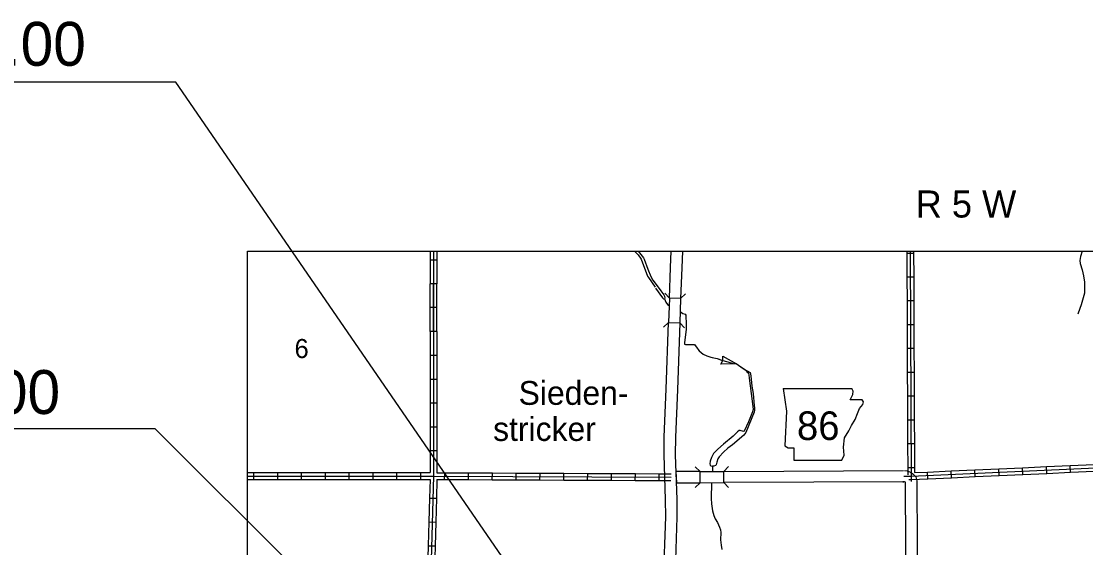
# Model space of a CAD drawing. Extents: x 982240 to 1103002, y 974866 to 1054902.
# Drawn here: x 1013608 to 1037189, y 1011477 to 1023147 of the extents above; entities that cross this region are included whole.
import ezdxf

# ---------------------------------------------------------------- set-up
doc = ezdxf.new("R2010")
doc.units = 0
for name, color, linetype in [('10', 7, 'Continuous'), ('15', 7, 'Continuous'), ('21', 7, 'Continuous'), ('24', 7, 'Continuous'), ('32', 7, 'Continuous'), ('35', 7, 'Continuous'), ('37', 7, 'Continuous'), ('43', 7, 'Continuous'), ('5', 7, 'Continuous'), ('R_Draft', 7, 'Continuous')]:
    doc.layers.add(name, color=color, linetype=linetype)

msp = doc.modelspace()

# ---------------------------------------------------------------- linework, layer by layer
at = {"layer": '10'}
for p, q in [((1028645, 1013167), (1028111, 1013164)), ((1028111, 1013164), (1028120, 1012914)), ((1028645, 1012917), (1028645, 1013167)), ((1029173, 1012919), (1029173, 1013169)), ((1028120, 1012914), (1028645, 1012917)), ((1028645, 1012917), (1028645, 1012917)), ((1033139, 1012939), (1033157, 1012938))]:
    msp.add_line(p, q, dxfattribs=at)
for points in [[(1028645, 1013167), (1029173, 1013169)], [(1029173, 1013169), (1033156, 1013188)], [(1033174, 1013187), (1033237, 1013178), (1033309, 1013153), (1033362, 1013117), (1033422, 1013046), (1033449, 1012962), (1033470, 1008617)], [(1028645, 1012917), (1029173, 1012919)], [(1033157, 1012938), (1029173, 1012919)], [(1033220, 1008616), (1033199, 1012923), (1033194, 1012928), (1033178, 1012934), (1033139, 1012939)]]:
    msp.add_lwpolyline(points, dxfattribs=at)
at = {"layer": '15'}
for p, q in [((1028215, 1017000), (1027965, 1017009)), ((1027946, 1016469), (1028196, 1016460))]:
    msp.add_line(p, q, dxfattribs=at)
for points in [[(1027965, 1017009), (1027989, 1017690), (1028005, 1018049)], [(1028256, 1018049), (1028239, 1017680), (1028215, 1017000)], [(1027965, 1017009), (1027946, 1016469)], [(1028215, 1017000), (1028196, 1016460)], [(1027488, 1005912), (1027591, 1006325), (1027648, 1006626), (1027676, 1006827), (1027714, 1007377), (1027838, 1010743), (1027884, 1012160), (1027883, 1012544), (1027847, 1013535), (1027848, 1013935), (1027894, 1014988), (1027946, 1016469)], [(1028196, 1016460), (1028144, 1014978), (1028098, 1013929), (1028097, 1013539), (1028133, 1012549), (1028134, 1012156), (1028088, 1010735), (1027964, 1007364), (1027924, 1006801), (1027895, 1006586), (1027836, 1006271), (1027730, 1005850)]]:
    msp.add_lwpolyline(points, dxfattribs=at)
at = {"layer": '21'}
for p, q in [((1030484, 1015009), (1030561, 1014502)), ((1032041, 1014950), (1032006, 1015008)), ((1031973, 1014755), (1032032, 1014874)), ((1032235, 1014755), (1031973, 1014755)), ((1032032, 1014874), (1032041, 1014950)), ((1032269, 1014713), (1032235, 1014755)), ((1030561, 1014502), (1030527, 1013732)), ((1032134, 1014451), (1032176, 1014561)), ((1032176, 1014561), (1032252, 1014654)), ((1032252, 1014654), (1032269, 1014713)), ((1031999, 1014189), (1032083, 1014316)), ((1032083, 1014316), (1032134, 1014451)), ((1031846, 1013910), (1031939, 1014070)), ((1031939, 1014070), (1031999, 1014189)), ((1031821, 1013707), (1031846, 1013910)), ((1030527, 1013732), (1030594, 1013690)), ((1030594, 1013690), (1030721, 1013690)), ((1030721, 1013690), (1030721, 1013419)), ((1031838, 1013529), (1031821, 1013707)), ((1030721, 1013419), (1031787, 1013419)), ((1031787, 1013419), (1031838, 1013529))]:
    msp.add_line(p, q, dxfattribs=at)
msp.add_lwpolyline([(1030484, 1015009), (1032006, 1015008)], dxfattribs=at)
at = {"layer": '32'}
for p, q in [((1022667, 1017855), (1022817, 1017855)), ((1033376, 1018002), (1033226, 1018002)), ((1022815, 1017327), (1022665, 1017327)), ((1033378, 1017474), (1033228, 1017474)), ((1033380, 1016946), (1033230, 1016946)), ((1022815, 1016799), (1022665, 1016799)), ((1033383, 1016418), (1033233, 1016418)), ((1022815, 1016271), (1022665, 1016271)), ((1022667, 1015743), (1022817, 1015743)), ((1033385, 1015890), (1033235, 1015890)), ((1022667, 1015215), (1022817, 1015215)), ((1033387, 1015362), (1033237, 1015362)), ((1033389, 1014834), (1033239, 1014834)), ((1022667, 1014687), (1022817, 1014687)), ((1033392, 1014306), (1033242, 1014306)), ((1022667, 1014159), (1022817, 1014159)), ((1033394, 1013778), (1033244, 1013778)), ((1022667, 1013631), (1022817, 1013631)), ((1022667, 1013631), (1022667, 1013141)), ((1022817, 1013631), (1022817, 1013140)), ((1018763, 1012991), (1018763, 1013141)), ((1019291, 1012991), (1019291, 1013141)), ((1019819, 1012991), (1019819, 1013141)), ((1020347, 1012991), (1020347, 1013141)), ((1020875, 1012991), (1020875, 1013141)), ((1021403, 1012991), (1021403, 1013141)), ((1021931, 1012991), (1021931, 1013141)), ((1022459, 1012991), (1022459, 1013141)), ((1022459, 1013141), (1022667, 1013141)), ((1022817, 1013140), (1022988, 1013139)), ((1022987, 1012989), (1022988, 1013139)), ((1023515, 1012987), (1023516, 1013137)), ((1024043, 1012984), (1024044, 1013134)), ((1024571, 1012982), (1024572, 1013132)), ((1025099, 1012979), (1025100, 1013129)), ((1025627, 1012977), (1025628, 1013127)), ((1026155, 1012974), (1026156, 1013124)), ((1026683, 1012972), (1026684, 1013122)), ((1027211, 1012969), (1027212, 1013119)), ((1027739, 1012966), (1027740, 1013116)), ((1033396, 1013250), (1033246, 1013250)), ((1033396, 1013250), (1033396, 1013141)), ((1033396, 1013141), (1033681, 1013154)), ((1033688, 1013004), (1033681, 1013154)), ((1034215, 1013028), (1034208, 1013178)), ((1034743, 1013053), (1034736, 1013202)), ((1035270, 1013077), (1035263, 1013227)), ((1035797, 1013101), (1035790, 1013251)), ((1036325, 1013125), (1036318, 1013275)), ((1036852, 1013150), (1036845, 1013300)), ((1022459, 1012991), (1022665, 1012991)), ((1022665, 1012991), (1022653, 1012578)), ((1022815, 1012990), (1022803, 1012573)), ((1022815, 1012990), (1022987, 1012989)), ((1022653, 1012578), (1022803, 1012573)), ((1022639, 1012050), (1022789, 1012046)), ((1022624, 1011522), (1022774, 1011518))]:
    msp.add_line(p, q, dxfattribs=at)
for points in [[(1022740, 1018049), (1022741, 1013064), (1022667, 1010407), (1022655, 1010251), (1022641, 1009890)], [(1022666, 1018049), (1022667, 1017855)], [(1022816, 1018049), (1022817, 1017855)], [(1033226, 1018049), (1033226, 1018002)], [(1033302, 1018049), (1033324, 1012943)], [(1033376, 1018049), (1033376, 1018002)], [(1022667, 1017855), (1022665, 1017327)], [(1022817, 1017855), (1022815, 1017327)], [(1033226, 1018002), (1033228, 1017474)], [(1033376, 1018002), (1033378, 1017474)], [(1022665, 1016799), (1022665, 1017327)], [(1022740, 1016271), (1022740, 1017327)], [(1022815, 1016799), (1022815, 1017327)], [(1033228, 1017474), (1033230, 1016946)], [(1033378, 1017474), (1033380, 1016946)], [(1033230, 1016946), (1033233, 1016418)], [(1033380, 1016946), (1033383, 1016418)], [(1022665, 1016271), (1022665, 1016799)], [(1022815, 1016271), (1022815, 1016799)], [(1033233, 1016418), (1033235, 1015890)], [(1033383, 1016418), (1033385, 1015890)], [(1022665, 1016271), (1022667, 1015743)], [(1022815, 1016271), (1022817, 1015743)], [(1022667, 1015743), (1022667, 1015215)], [(1022817, 1015743), (1022817, 1015215)], [(1033235, 1015890), (1033237, 1015362)], [(1033385, 1015890), (1033387, 1015362)], [(1022667, 1015215), (1022667, 1014687)], [(1022817, 1015215), (1022817, 1014687)], [(1033237, 1015362), (1033239, 1014834)], [(1033387, 1015362), (1033389, 1014834)], [(1033239, 1014834), (1033242, 1014306)], [(1033389, 1014834), (1033392, 1014306)], [(1022667, 1014687), (1022667, 1014159)], [(1022817, 1014687), (1022817, 1014159)], [(1033242, 1014306), (1033244, 1013778)], [(1033392, 1014306), (1033394, 1013778)], [(1022667, 1014159), (1022667, 1013631)], [(1022817, 1014159), (1022817, 1013631)], [(1033244, 1013778), (1033246, 1013250)], [(1033394, 1013778), (1033396, 1013250)], [(1033157, 1013063), (1033323, 1013061), (1038730, 1013310)], [(1036845, 1013300), (1037373, 1013324)], [(1018617, 1013141), (1018763, 1013141)], [(1018763, 1013141), (1019291, 1013141)], [(1019291, 1013141), (1019819, 1013141)], [(1019819, 1013141), (1020347, 1013141)], [(1020347, 1013141), (1020875, 1013141)], [(1020875, 1013141), (1021403, 1013141)], [(1021403, 1013141), (1021931, 1013141)], [(1021931, 1013141), (1022459, 1013141)], [(1022988, 1013139), (1023516, 1013137)], [(1023516, 1013137), (1024044, 1013134)], [(1024044, 1013134), (1024572, 1013132)], [(1024572, 1013132), (1025100, 1013129)], [(1025100, 1013129), (1025628, 1013127)], [(1025628, 1013127), (1026156, 1013124)], [(1026156, 1013124), (1026684, 1013122)], [(1026684, 1013122), (1027212, 1013119)], [(1027212, 1013119), (1027740, 1013116)], [(1027740, 1013116), (1028002, 1013115)], [(1033246, 1013250), (1033247, 1013090)], [(1033681, 1013154), (1034208, 1013178)], [(1034208, 1013178), (1034736, 1013202)], [(1034736, 1013202), (1035263, 1013227)], [(1034743, 1013053), (1035270, 1013077)], [(1035263, 1013227), (1035790, 1013251)], [(1035270, 1013077), (1035797, 1013101)], [(1035790, 1013251), (1036318, 1013275)], [(1035797, 1013101), (1036325, 1013125)], [(1036318, 1013275), (1036845, 1013300)], [(1036325, 1013125), (1036852, 1013150)], [(1036852, 1013150), (1037380, 1013174)], [(1018617, 1013064), (1022741, 1013064), (1028002, 1013039)], [(1018617, 1012991), (1018763, 1012991)], [(1018763, 1012991), (1019291, 1012991)], [(1019291, 1012991), (1019819, 1012991)], [(1019819, 1012991), (1020347, 1012991)], [(1020347, 1012991), (1020875, 1012991)], [(1020875, 1012991), (1021403, 1012991)], [(1021403, 1012991), (1021931, 1012991)], [(1021931, 1012991), (1022459, 1012991)], [(1022987, 1012989), (1023515, 1012987)], [(1023515, 1012987), (1024043, 1012984)], [(1024043, 1012984), (1024571, 1012982)], [(1024571, 1012982), (1025099, 1012979)], [(1025099, 1012979), (1025627, 1012977)], [(1025627, 1012977), (1026155, 1012974)], [(1026155, 1012974), (1026683, 1012972)], [(1026683, 1012972), (1027211, 1012969)], [(1027211, 1012969), (1027739, 1012966)], [(1027739, 1012966), (1028001, 1012965)], [(1033269, 1012988), (1033324, 1012987), (1033688, 1013004)], [(1033688, 1013004), (1034215, 1013028)], [(1034215, 1013028), (1034743, 1013053)], [(1022653, 1012578), (1022639, 1012050)], [(1022803, 1012573), (1022789, 1012046)], [(1022639, 1012050), (1022624, 1011522)], [(1022789, 1012046), (1022774, 1011518)], [(1022624, 1011522), (1022609, 1010994)], [(1022774, 1011518), (1022759, 1010990)]]:
    msp.add_lwpolyline(points, dxfattribs=at)
at = {"layer": '35'}
for points in [[(1027192, 1018049), (1027275, 1017971), (1027339, 1017873), (1027480, 1017500), (1027500, 1017467), (1027649, 1017254)], [(1027273, 1018049), (1027390, 1017902), (1027408, 1017871), (1027491, 1017649), (1027554, 1017489), (1027601, 1017406)], [(1037110, 1018049), (1037072, 1017933), (1037061, 1017846), (1037070, 1017775), (1037113, 1017634), (1037142, 1017501), (1037159, 1017365), (1037165, 1017266), (1037159, 1017123), (1037092, 1016863), (1037020, 1016673), (1037016, 1016657)], [(1027601, 1017406), (1027717, 1017249), (1027776, 1017170), (1027846, 1017080), (1027859, 1017051), (1027865, 1017007), (1027859, 1016993), (1027886, 1016917), (1027925, 1016872), (1027959, 1016846)], [(1027660, 1017232), (1027812, 1017017), (1027836, 1016997), (1027859, 1016993)], [(1028205, 1016716), (1028264, 1016668), (1028317, 1016651), (1028329, 1016631), (1028337, 1016425), (1028337, 1016385)], [(1028337, 1016385), (1028335, 1016324), (1028301, 1016018), (1028304, 1015986), (1028321, 1015978)], [(1029679, 1015400), (1029676, 1015394), (1029683, 1015379), (1029701, 1015364), (1029720, 1015340), (1029728, 1015311), (1029733, 1015237), (1029801, 1014725), (1029821, 1014542), (1029808, 1014490), (1029717, 1014267), (1029624, 1014058), (1029610, 1014050), (1029537, 1014076), (1029514, 1014074), (1029478, 1014044), (1029380, 1013947), (1029162, 1013776)], [(1029679, 1015400), (1029691, 1015399), (1029753, 1015360), (1029768, 1015288), (1029796, 1015060), (1029820, 1014892), (1029843, 1014632), (1029852, 1014579), (1029851, 1014526), (1029844, 1014483), (1029656, 1014031), (1029616, 1013975), (1029362, 1013759), (1029258, 1013683)], [(1029162, 1013776), (1029037, 1013662), (1028945, 1013563), (1028898, 1013478), (1028871, 1013398), (1028861, 1013337), (1028870, 1013304), (1028881, 1013295), (1028924, 1013284), (1028923, 1013170)], [(1029258, 1013683), (1029163, 1013595), (1029067, 1013489), (1029042, 1013450), (1029017, 1013375), (1029005, 1013317), (1028989, 1013296), (1028951, 1013284), (1028924, 1013284)], [(1028898, 1012918), (1028894, 1012565), (1028902, 1012449), (1028924, 1012295), (1028952, 1012188), (1028983, 1012117), (1029031, 1012039), (1029079, 1011936), (1029099, 1011870), (1029104, 1011814), (1029098, 1011652), (1029112, 1011534), (1029131, 1011435)]]:
    msp.add_lwpolyline(points, dxfattribs=at)
at = {"layer": '37'}
for points in [[(1027965, 1017009), (1027863, 1017119)], [(1028325, 1017102), (1028215, 1017000)], [(1027836, 1016367), (1027946, 1016469)], [(1028196, 1016460), (1028298, 1016351)], [(1028539, 1013273), (1028645, 1013167)], [(1029173, 1013169), (1029279, 1013275)], [(1028645, 1012917), (1028539, 1012811)], [(1029279, 1012813), (1029173, 1012919)]]:
    msp.add_lwpolyline(points, dxfattribs=at)
at = {"layer": '43'}
for p, q in [((1029151, 1015720), (1029450, 1015551)), ((1029152, 1015629), (1029152, 1015721)), ((1029106, 1015549), (1029152, 1015628)), ((1029450, 1015551), (1029107, 1015548)), ((1029152, 1015628), (1029152, 1015629))]:
    msp.add_line(p, q, dxfattribs=at)
for points in [[(1028321, 1015978), (1028521, 1015978), (1028578, 1015900), (1028628, 1015840), (1028717, 1015766), (1028793, 1015728), (1028885, 1015700), (1029026, 1015668), (1029118, 1015638), (1029257, 1015594), (1029381, 1015562), (1029443, 1015551), (1029464, 1015543), (1029498, 1015522), (1029679, 1015400)], [(1028321, 1015978), (1028519, 1015978)], [(1028599, 1015875), (1028628, 1015840), (1028717, 1015766), (1028793, 1015728), (1028885, 1015700), (1028938, 1015688)], [(1029065, 1015655), (1029118, 1015638), (1029257, 1015594), (1029381, 1015562), (1029443, 1015551), (1029449, 1015551)], [(1029559, 1015481), (1029679, 1015400)]]:
    msp.add_lwpolyline(points, dxfattribs=at)
at = {"layer": 'R_Draft'}
for p, q in [((1017029, 1021794), (1005180, 1021794)), ((1027704, 1006272), (1017029, 1021794)), ((1016573, 1014109), (1004674, 1014109)), ((1027199, 1003525), (1016573, 1014109))]:
    msp.add_line(p, q, dxfattribs=at)
msp.add_lwpolyline([(1018617, 1018049), (1063840, 1018049), (1063840, 987556), (1018617, 987556)], close=True, dxfattribs=at)
msp.add_lwpolyline([(1018617, 1018049), (1063840, 1018049), (1063840, 987556), (1018617, 987556)], close=True, dxfattribs=at)

# ---------------------------------------------------------------- texts
at = {"layer": '21'}
msp.add_text('86', height=633.6, dxfattribs=at).set_placement((1030792, 1013865))
at = {"layer": '24'}
for s, p in [('Sieden-', (1024626, 1014644)), ('stricker', (1024061, 1013844))]:
    msp.add_text(s, height=528, dxfattribs=at).set_placement(p)
at = {"layer": '5'}
msp.add_text('6', height=422, dxfattribs=at).set_placement((1019661, 1015682))
at = {"layer": 'R_Draft'}
for s, height, p in [('STA. 233+00.00 ', 972, (1005608, 1022160)), ('R 5 W', 600, (1033422, 1018796)), ('STA. 205+00.00', 972, (1005038, 1014442))]:
    msp.add_text(s, height=height, dxfattribs=at).set_placement(p)

doc.saveas('drawing.dxf')
